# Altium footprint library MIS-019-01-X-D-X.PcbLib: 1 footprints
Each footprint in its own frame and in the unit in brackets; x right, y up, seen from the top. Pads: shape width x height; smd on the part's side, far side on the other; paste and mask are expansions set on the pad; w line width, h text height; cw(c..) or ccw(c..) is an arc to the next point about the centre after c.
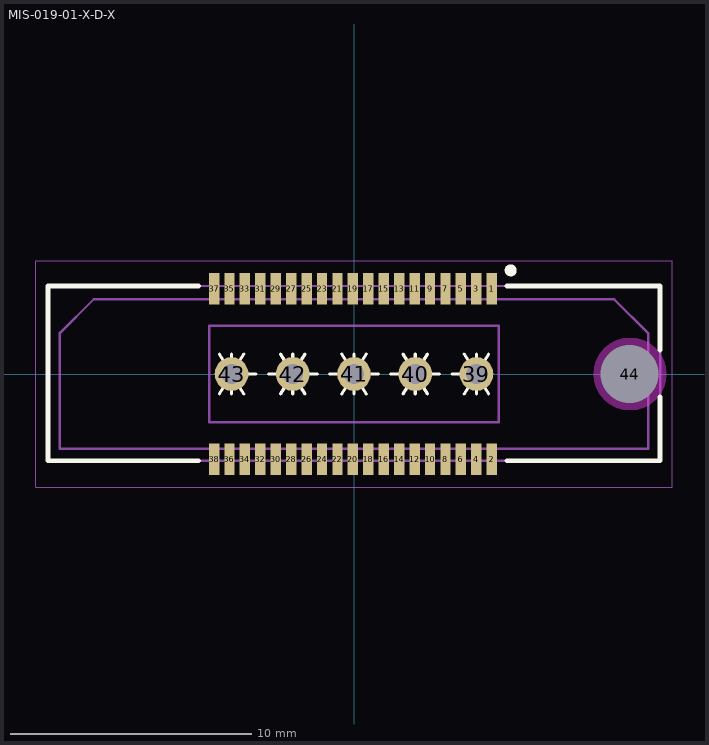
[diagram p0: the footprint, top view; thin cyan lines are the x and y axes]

## MIS-019-01-X-D-X [mm] "0.635mm pitch, 38 pin, mixed technology high speed socket"
height 3.63
pads (44):
  rect 0.43x1.3 smd mask+0: 1(5.715,3.53) 2(5.715,-3.53) 3(5.075,3.53) 4(5.075,-3.53) 5(4.435,3.53) 6(4.435,-3.53) 7(3.795,3.53) 8(3.795,-3.53) 9(3.155,3.53) 10(3.155,-3.53) 11(2.515,3.53) 12(2.515,-3.53) 13(1.875,3.53) 14(1.875,-3.53) 15(1.235,3.53) 16(1.235,-3.53) 17(0.595,3.53) 18(0.595,-3.53) 19(-0.045,3.53) 20(-0.045,-3.53) 21(-0.685,3.53) 22(-0.685,-3.53) 23(-1.325,3.53) 24(-1.325,-3.53) 25(-1.965,3.53) 26(-1.965,-3.53) 27(-2.605,3.53) 28(-2.605,-3.53) 29(-3.245,3.53) 30(-3.245,-3.53) 31(-3.885,3.53) 32(-3.885,-3.53) 33(-4.525,3.53) 34(-4.525,-3.53) 35(-5.165,3.53) 36(-5.165,-3.53) 37(-5.805,3.53) 38(-5.805,-3.53)
  round 1.4 hole 0.85 mask+0: 39(5.08,0) 40(2.54,0) 41(0,0) 42(-2.54,0) 43(-5.08,0)
  round 1 hole 2.4 unplated mask+0: 44(11.43,0)
Top Overlay:
  circle w0.25: c6.5,4.3 r0.125
  lines w0.127: -5.588,-0.826 -4.572,0.826 ; -5.588,0.826 -4.572,-0.826 ; -5.08,-0.826 -5.08,0.826 ; -5.08,0 -4.064,0 ; -3.556,0 -2.54,0 -1.524,0 ; -3.048,-0.826 -2.032,0.826 ; -3.048,0.826 -2.032,-0.826 ; -2.54,-0.826 -2.54,0.826 ; -1.016,0 0,0 1.016,0 ; -0.508,-0.826 0.508,0.826 ; -0.508,0.826 0.508,-0.826 ; 0,-0.826 0,0.826 ; 1.524,0 2.54,0 3.556,0 ; 2.032,-0.826 3.048,0.826 ; 2.032,0.826 3.048,-0.826 ; 2.54,-0.826 2.54,0.826 ; 4.064,0 5.08,0 ; 4.572,-0.826 5.588,0.826 ; 4.572,0.826 5.588,-0.826 ; 5.08,-0.826 5.08,0.826
  lines w0.2: -6.45,-3.6 -12.7,-3.6 -12.7,3.65 -6.45,3.65 ; 6.35,-3.6 12.7,-3.6 12.7,-0.95 ; 6.35,3.65 12.7,3.65 12.7,1
Keep-Out Layer:
  pour cut-out: 12.958,0 12.929,0.294 12.843,0.577 12.704,0.838 12.516,1.066 12.288,1.254 12.027,1.393 11.744,1.479 11.45,1.508 11.156,1.479 10.873,1.393 10.612,1.254 10.384,1.066 10.196,0.838 10.057,0.577 9.971,0.294 9.942,0 9.971,-0.294 10.057,-0.577 10.196,-0.838 10.384,-1.066 10.612,-1.254 10.873,-1.393 11.156,-1.479 11.45,-1.508 11.744,-1.479 12.027,-1.393 12.288,-1.254 12.516,-1.066 12.704,-0.838 12.843,-0.577 12.929,-0.294
Mechanical 12:
  lines w0.001: -12.7,-3.6 12.7,-3.6 12.7,3.65 -12.7,3.65 -12.7,-3.6
Mechanical 13:
  lines w0.1: -12.7,-3.6 12.7,-3.6 12.7,3.65 -12.7,3.65 -12.7,-3.6 ; -12.2,-3.1 12.2,-3.1 12.2,1.703 10.792,3.1 -10.794,3.1 -12.2,1.704 -12.2,-3.1 ; -6,-2 6,-2 6,2 -6,2 -6,-2
  text ".Designator" at 0.254,0.254 h1.52
Mechanical 15:
  lines w0.05: -0.5,0 0.5,0 ; 0,-0.5 0,0.5 ; -13.2,-4.7 13.2,-4.7 13.2,4.7 -13.2,4.7 -13.2,-4.7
